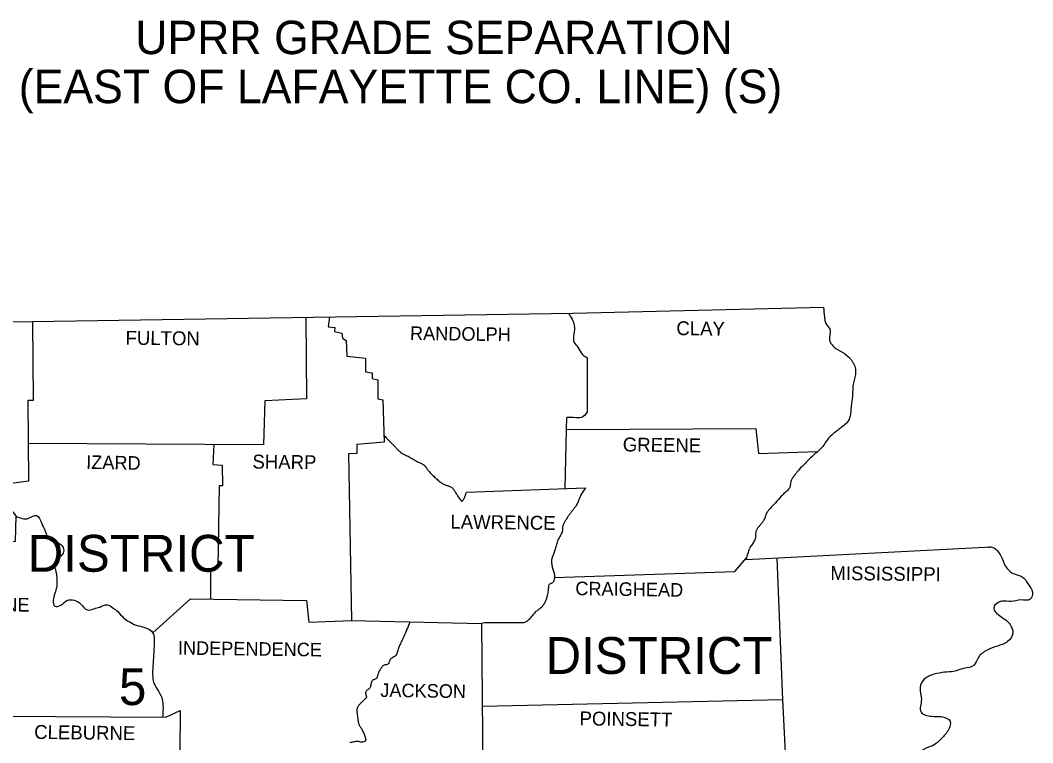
# Model space of a CAD drawing. Extents: x 164 to 3385, y 68 to 2119.
# Drawn here: x 2994.5 to 3298, y 1824.7 to 2041.1 of the extents above; entities that cross this region are included whole.
import ezdxf

# ---------------------------------------------------------------- set-up
doc = ezdxf.new("R2010")
doc.units = 0
doc.layers.add('Default', color=7, linetype='Continuous')
doc.layers.add('R_Border', color=7, linetype='Continuous')

msp = doc.modelspace()

# ---------------------------------------------------------------- linework, layer by layer
at = {"layer": 'Default'}
for p, q in [((3158.29, 1918.57), (3158.37, 1922.15)), ((3212.08, 1879.57), (3213.12, 1882.79))]:
    msp.add_line(p, q, dxfattribs=at)
for points in [[(2704.43, 1950.7), (2860.9, 1950.6), (2998.22, 1950.89), (3160.21, 1953.41), (3235.3, 1955.15)], [(3080.18, 1952.17), (3080.38, 1927.77), (3067.8, 1927.09), (3067.41, 1913.93), (2996.92, 1914.32)], [(3087.23, 1952.28), (3086.86, 1949.35), (3088.8, 1949.06), (3088.7, 1947.89), (3090.92, 1947.41), (3091.12, 1945.86), (3092.18, 1945.18), (3092.47, 1940.54), (3097.99, 1939.96), (3097.99, 1935.8), (3100.02, 1935.51), (3100.02, 1933.86), (3101.76, 1933.38), (3101.67, 1927.77), (3103.21, 1927.48), (3103.6, 1914.8), (3095.38, 1914.02), (3095.47, 1911.31), (3092.96, 1911.22), (3093.83, 1861.28), (3132.83, 1860.41), (3133.5, 1782.8), (3108.05, 1782.13), (3107.55, 1795.77)], [(2998.21, 1950.89), (2998.41, 1927.28), (2996.77, 1927.19), (2997.06, 1903.09), (2990.28, 1902.12), (2990.86, 1895.64), (2993.19, 1892.64), (2992.99, 1884.99), (2979.83, 1884.51), (2979.35, 1872.7), (2967.35, 1872.32), (2966.77, 1857.99), (2967.45, 1856.83), (2967.74, 1833.99), (2988.45, 1832.64), (2988.16, 1781.64), (3004.61, 1781.16), (3004.61, 1729.29), (2991.64, 1728.32), (2990.67, 1716.9), (2968.9, 1716.81)], [(3164.47, 1940.06), (3164.47, 1923.7)], [(3157.86, 1900.84), (3158.29, 1918.57), (3158.37, 1918.57), (3214.98, 1918.86), (3215.76, 1911.31), (3233.52, 1911.96)], [(3052.52, 1914.01), (3052.31, 1908.02), (3055.02, 1907.83), (3055.12, 1901.64), (3054.15, 1901.64), (3053.76, 1877.25), (3051.54, 1876.28), (3051.54, 1867.68)], [(3128.28, 1899.8), (3163.95, 1901.05)], [(3212.08, 1879.57), (3285.53, 1883.35)], [(3154.65, 1874.24), (3208.69, 1875.99), (3212.25, 1880.08)], [(3221.35, 1880.05), (3223.01, 1837.58), (3224.98, 1797.93)], [(3034.31, 1857.62), (3045.54, 1867.77), (3080.38, 1867.28), (3081.05, 1860.8), (3093.83, 1861.28)], [(3145.5, 1860.61), (3133.7, 1860.61), (3132.83, 1860.41)], [(3223.01, 1837.58), (3133.04, 1835.52)], [(2988.45, 1832.64), (3038.19, 1832.35), (3042.44, 1834.38), (3042.15, 1796.54), (3039.25, 1795.29), (3036.64, 1793.06), (3035.77, 1792.19), (3035.67, 1781.35), (2998.02, 1781.35)]]:
    msp.add_lwpolyline(points, dxfattribs=at)
for points in [[(3235.3, 1955.15), (3235.39, 1954.08), (3235.5, 1953.02), (3235.63, 1951.96), (3235.79, 1950.89), (3236.01, 1950.29), (3236.41, 1949.75), (3236.83, 1949.23), (3237.14, 1948.67), (3237.27, 1947.69), (3237.15, 1946.63), (3237.07, 1945.57), (3237.14, 1945.07), (3237.34, 1944.6), (3238.07, 1943.65), (3238.98, 1942.86), (3239.67, 1942.4), (3240.39, 1942), (3241.1, 1941.59), (3241.79, 1941.12), (3243.18, 1939.88), (3243.78, 1939.16), (3244.05, 1938.75), (3244.3, 1938.31), (3244.65, 1937.49), (3244.86, 1936.67), (3244.93, 1935.84), (3244.88, 1935.02), (3244.72, 1934.18), (3244.48, 1933.34), (3244.25, 1932.49), (3244.11, 1931.64), (3244.06, 1930.7), (3244.02, 1929.75), (3243.99, 1928.81), (3243.92, 1927.86), (3243.53, 1924.57), (3243.35, 1923.06), (3243.2, 1922.31), (3243.09, 1921.94), (3242.95, 1921.57), (3241.94, 1920.23), (3240.63, 1919.15), (3240.07, 1918.71), (3239.51, 1918.29), (3238.95, 1917.86), (3238.4, 1917.41), (3236.37, 1915.38), (3235.99, 1914.86), (3235.66, 1914.3), (3235.33, 1913.74), (3234.92, 1913.25), (3232.4, 1910.93), (3229.89, 1908.51), (3227.85, 1906.38), (3227.3, 1905.74), (3226.78, 1905.07), (3226.29, 1904.37), (3225.82, 1903.67), (3225.52, 1902.94), (3225.38, 1902.14), (3225.22, 1901.35), (3225.07, 1900.99), (3224.85, 1900.67), (3224.32, 1900.12), (3223.74, 1899.6), (3223.17, 1899.09), (3222.63, 1898.54), (3220.89, 1896.61), (3218.56, 1893.99), (3218.18, 1893.4), (3217.92, 1892.72), (3217.69, 1892.03), (3217.4, 1891.38), (3216.88, 1890.61), (3216.28, 1889.89), (3215.68, 1889.16), (3215.18, 1888.38), (3214.97, 1887.68), (3214.91, 1886.94), (3214.87, 1886.18), (3214.69, 1885.48), (3214.38, 1884.88), (3213.99, 1884.3), (3213.6, 1883.73), (3213.24, 1883.15), (3213.12, 1882.79)], [(3158.84, 1953.39), (3160.6, 1949.73), (3160.5, 1947.12), (3160.5, 1944.7), (3161.76, 1943.06), (3163.02, 1941.02), (3164.47, 1940.06)], [(3164.47, 1923.7), (3162.82, 1922.15), (3160.4, 1922.15), (3158.37, 1922.15)], [(3103.54, 1916.84), (3105.15, 1915.13), (3106.79, 1913.44), (3107.02, 1913.21), (3107.69, 1912.5), (3108.15, 1912.04), (3108.39, 1911.82), (3108.51, 1911.71), (3108.63, 1911.61), (3109.13, 1911.28), (3109.67, 1911.03), (3110.23, 1910.8), (3110.76, 1910.54), (3112.02, 1909.82), (3113.28, 1909.09), (3113.83, 1908.8), (3114.4, 1908.53), (3115.24, 1908.1), (3115.37, 1908.01), (3115.5, 1907.93), (3115.93, 1907.53), (3116.27, 1907.05), (3116.59, 1906.55), (3116.77, 1906.31), (3116.96, 1906.09), (3117.95, 1905.06), (3118.99, 1904.06), (3119.48, 1903.62), (3119.98, 1903.21), (3120.5, 1902.8), (3121.02, 1902.41), (3121.81, 1902), (3122.69, 1901.72), (3123.53, 1901.4), (3123.9, 1901.17), (3124.07, 1901.03), (3124.21, 1900.86), (3124.5, 1900.46), (3124.76, 1900.05), (3125.01, 1899.63), (3125.28, 1899.22), (3125.46, 1898.95), (3125.64, 1898.67), (3126, 1898.1), (3126.37, 1897.59), (3126.55, 1897.37), (3126.64, 1897.27), (3126.68, 1897.23), (3126.73, 1897.19), (3126.84, 1897.12), (3126.95, 1897.11), (3127.16, 1897.23), (3127.58, 1897.92), (3127.96, 1898.9), (3128.13, 1899.38), (3128.28, 1899.8)], [(3163.95, 1901.05), (3163.14, 1899.87), (3162.44, 1898.64), (3162.14, 1897.96), (3161.88, 1897.27), (3161.61, 1896.58), (3161.28, 1895.93), (3160.73, 1895.13), (3160.14, 1894.37), (3159.53, 1893.61), (3158.95, 1892.83), (3158.02, 1891.37), (3157.59, 1890.61), (3157.21, 1889.83), (3157.08, 1889.34), (3157.05, 1888.82), (3157.03, 1888.3), (3156.92, 1887.8), (3156.61, 1887.12), (3156.23, 1886.45), (3155.86, 1885.79), (3155.57, 1885.09), (3155.36, 1884.42), (3155.18, 1883.74), (3154.99, 1883.05), (3154.79, 1882.38), (3154.58, 1881.8), (3154.35, 1881.22), (3154.12, 1880.65), (3153.92, 1880.06), (3153.81, 1879.46), (3153.8, 1878.85), (3153.84, 1878.24), (3153.92, 1877.64), (3154.05, 1877.03), (3154.25, 1876.43), (3154.45, 1875.82), (3154.6, 1875.22), (3154.66, 1874.67), (3154.64, 1874.11), (3154.56, 1873.54), (3154.49, 1873.27), (3154.41, 1872.99), (3154.11, 1872.66), (3153.66, 1872.46), (3153.22, 1872.26), (3152.95, 1871.93), (3152.88, 1871.59), (3152.83, 1871.24), (3152.76, 1870.53), (3152.69, 1869.82), (3152.57, 1869.12), (3152.31, 1868.15), (3151.99, 1867.19), (3151.45, 1866.16), (3151.11, 1865.69), (3150.73, 1865.25), (3150.29, 1864.86), (3149.81, 1864.51), (3149.33, 1864.17), (3148.89, 1863.8), (3148.39, 1863.26), (3147.93, 1862.69), (3147.46, 1862.12), (3146.95, 1861.57), (3146.28, 1861.04), (3145.9, 1860.81), (3145.5, 1860.61)], [(2993.19, 1892.64), (2997.06, 1891.96), (2999.38, 1892.83), (3001.03, 1890.32), (3001.9, 1888.38), (3003.35, 1885.57), (3005.67, 1884.7), (3007.41, 1883.15), (3007.41, 1881.51), (3005.86, 1879.96), (3004.7, 1878.41), (3005.09, 1876.57), (3005.48, 1874.06), (3005.48, 1871.64), (3004.9, 1869.41), (3004.41, 1867.38), (3004.9, 1865.64), (3006.73, 1865.93), (3008.67, 1867.38), (3010.7, 1867.38), (3012.64, 1866.32), (3014.67, 1864.48), (3016.7, 1864.86), (3018.35, 1865.35), (3020.67, 1866.03), (3022.31, 1865.15), (3023.77, 1863.99), (3025.51, 1862.16), (3027.15, 1860.99), (3029.28, 1859.93), (3031.9, 1859.25), (3034.31, 1857.61), (3034.7, 1854.8), (3034.6, 1852.38), (3034.41, 1849.38), (3034.22, 1846.09), (3034.51, 1842.9), (3035.57, 1840.77), (3036.93, 1838.25), (3037.31, 1835.93), (3037.22, 1832.25)], [(3284.46, 1883.25), (3285.53, 1883.35), (3288.82, 1879.86), (3290.27, 1876.96), (3292.4, 1875.32), (3294.82, 1874.45), (3296.66, 1872.22), (3297.91, 1869.8), (3297.24, 1867.67), (3294.53, 1867.48), (3291.53, 1866.99), (3288.62, 1867.09), (3286.3, 1865.15), (3288.43, 1862.54), (3291.24, 1860.12), (3292.01, 1857.51), (3290.46, 1854.99), (3287.37, 1853.64), (3284.37, 1852.48), (3281.66, 1850.16), (3280.4, 1847.93), (3277.4, 1846.96), (3274.3, 1846.09), (3271.59, 1845.8), (3268.5, 1845.22), (3265.5, 1843.77), (3264.24, 1841.25), (3264.63, 1837.67), (3264.53, 1833.9), (3267.72, 1832.64), (3270.53, 1832.54), (3273.24, 1831.09), (3272.95, 1828.96), (3270.92, 1826.25), (3268.5, 1824.12), (3266.08, 1823.06), (3263.85, 1821.03), (3264.63, 1819), (3266.66, 1817.64), (3268.11, 1815.41), (3267.92, 1813.38), (3265.59, 1811.93), (3263.08, 1812.51), (3261.24, 1814.93), (3259.11, 1815.71), (3257.27, 1816.58), (3255.14, 1815.32), (3255.14, 1812.51), (3254.37, 1809.51), (3255.05, 1807.29), (3255.92, 1804.19), (3255.82, 1801.87), (3255.05, 1798.58), (3253.4, 1795.19), (3251.47, 1794.13), (3250.69, 1797.8), (3250.3, 1800.8), (3249.14, 1802.54), (3247.59, 1802.64), (3245.56, 1801.19), (3243.34, 1798.96), (3240.53, 1796.54), (3238.88, 1794.13), (3239.76, 1791.13), (3241.88, 1790.35), (3243.53, 1790.93), (3244.4, 1792.87), (3246.05, 1793.16), (3247.59, 1790.16)], [(3111.31, 1860.89), (3110.44, 1858.71), (3109.5, 1856.54), (3109.17, 1855.81), (3108.83, 1855.09), (3108.48, 1854.36), (3108.15, 1853.64), (3107.91, 1853.02), (3107.72, 1852.38), (3107.52, 1851.74), (3107.28, 1851.12), (3106.92, 1850.68), (3106.41, 1850.34), (3105.88, 1850.04), (3105.64, 1849.87), (3105.44, 1849.67), (3105.27, 1849.36), (3105.16, 1848.99), (3105.05, 1848.62), (3104.86, 1848.32), (3104.49, 1848.12), (3104.04, 1848.04), (3103.58, 1847.96), (3103.21, 1847.74), (3103.03, 1847.51), (3102.85, 1847.28), (3102.52, 1846.81), (3102.23, 1846.31), (3101.96, 1845.8), (3101.79, 1845.37), (3101.67, 1844.92), (3101.55, 1844.48), (3101.38, 1844.06), (3101.1, 1843.81), (3100.71, 1843.66), (3100.32, 1843.51), (3100.02, 1843.28), (3099.89, 1843.05), (3099.79, 1842.79), (3099.66, 1842.22), (3099.54, 1841.66), (3099.41, 1841.27), (3099.34, 1841.16), (3099.07, 1840.85), (3098.71, 1840.58), (3098.35, 1840.31), (3098.09, 1839.99), (3098.03, 1839.54), (3098.17, 1839.01), (3098.29, 1838.5), (3098.18, 1838.06), (3098.1, 1837.97), (3098.02, 1837.88), (3097.47, 1837.38), (3097.08, 1837.06), (3096.73, 1836.7), (3096.4, 1836.35), (3096.07, 1835.98), (3095.78, 1835.6), (3095.66, 1835.38), (3095.57, 1835.16), (3095.45, 1834.09), (3095.57, 1833.03), (3095.64, 1832.32), (3095.72, 1831.61), (3095.85, 1830.91), (3095.94, 1830.56), (3096.05, 1830.22), (3096.26, 1829.79), (3096.52, 1829.38), (3096.78, 1828.99), (3097.02, 1828.58), (3097.49, 1827.52), (3097.7, 1826.98), (3097.89, 1826.45), (3098, 1826.1), (3098.06, 1825.73), (3098.02, 1825.38), (3097.93, 1825.23), (3097.87, 1825.16), (3097.8, 1825.09), (3097.2, 1824.87), (3096.59, 1824.92), (3095.98, 1825.07), (3095.68, 1825.11), (3095.38, 1825.09), (3094.87, 1825.01), (3094.36, 1824.92), (3093.85, 1824.82), (3093.34, 1824.7)]]:
    msp.add_spline(points, degree=3, dxfattribs=at)

# ---------------------------------------------------------------- texts
for s, height, rotation, p in [('RANDOLPH', 4.065, 359.2583, (3111.34, 1945.38)), ('CLAY', 4.161, 359.2258, (3191.18, 1946.83)), ('FULTON', 4.161, 359.4996, (3026.09, 1943.93)), ('GREENE', 4.162, 359.2361, (3175.11, 1911.99)), ('IZARD', 4.064, 358.9258, (3014.28, 1906.77)), ('SHARP', 4.161, 359.3905, (3064.12, 1906.86)), ('LAWRENCE', 4.162, 359.2678, (3123.44, 1888.86)), ('MISSISSIPPI', 4.1606, 359.3097, (3237.34, 1873.48)), ('CRAIGHEAD', 4.065, 359.1159, (3160.89, 1868.93)), ('STONE', 4.064, 359.4001, (2978.58, 1864.19)), ('INDEPENDENCE', 4.0637, 359.2187, (3041.77, 1851.12)), ('JACKSON', 4.064, 359.1352, (3102.44, 1838.45)), ('POINSETT', 4.161, 359.1987, (3162.15, 1829.93)), ('CLEBURNE', 4.161, 359.2535, (2998.7, 1825.87))]:
    msp.add_text(s, height=height, rotation=rotation, dxfattribs=at).set_placement(p)
for s, height, p in [('DISTRICT', 11.032, (2996.78, 1875.94)), ('DISTRICT', 11.032, (3151.99, 1845.32)), ('5', 11.03, (3024.14, 1836))]:
    msp.add_text(s, height=height, dxfattribs=at).set_placement(p)
at = {"layer": 'R_Border'}
for s, p in [('UPRR GRADE SEPARATION', (3029.01, 2031)), ('(EAST OF LAFAYETTE CO. LINE) (S)', (2994.09, 2016.31))]:
    msp.add_text(s, height=10, dxfattribs=at).set_placement(p)

doc.saveas('drawing.dxf')
